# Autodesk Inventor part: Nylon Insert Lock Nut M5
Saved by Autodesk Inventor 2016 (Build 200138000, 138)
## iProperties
Created: 2016-01
Part Number: Nylon Insert Lock Nut M5
Material: Generic
Document SubType Name: Modeling
Designer: John
Density: 1 g/cm^3
Appearance: Default
Author: John
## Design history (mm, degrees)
feature "CUT-EXTRUDE1"
body "Solid1"
